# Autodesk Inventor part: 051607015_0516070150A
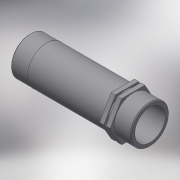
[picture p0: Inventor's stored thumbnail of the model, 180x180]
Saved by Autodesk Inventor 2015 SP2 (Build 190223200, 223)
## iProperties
Created: 2017-05
Part Number: 051607015_0516070150A
Material: Generic
Description: PLASSON RISER 1.1/2"-1.1/2"
Document SubType Name: Modeling
Designer: KIM
Mass: 20.3153 g
Surface Area: 184.457 cm^2
Volume: 20.3153 cm^3
Density: 1 g/cm^3
Appearance: Default
Author: KIM
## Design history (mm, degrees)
derived "051607.ipt"
feature "Solid1::051607.ipt"
tag "TaggingFeature1"
body "Solid1"
other parameters: "d1" = 47.803, "d3" = 38.2424, "d5" = 21, "d6" = 5.25, "d8" = 1.05, "d12" = 0, "d13" = 2.625, "d15" = 21, "d17" = 0, "d18" = 47.803, "R_" = 47.803, "l_2" = 21, "R_1" = 47.803
